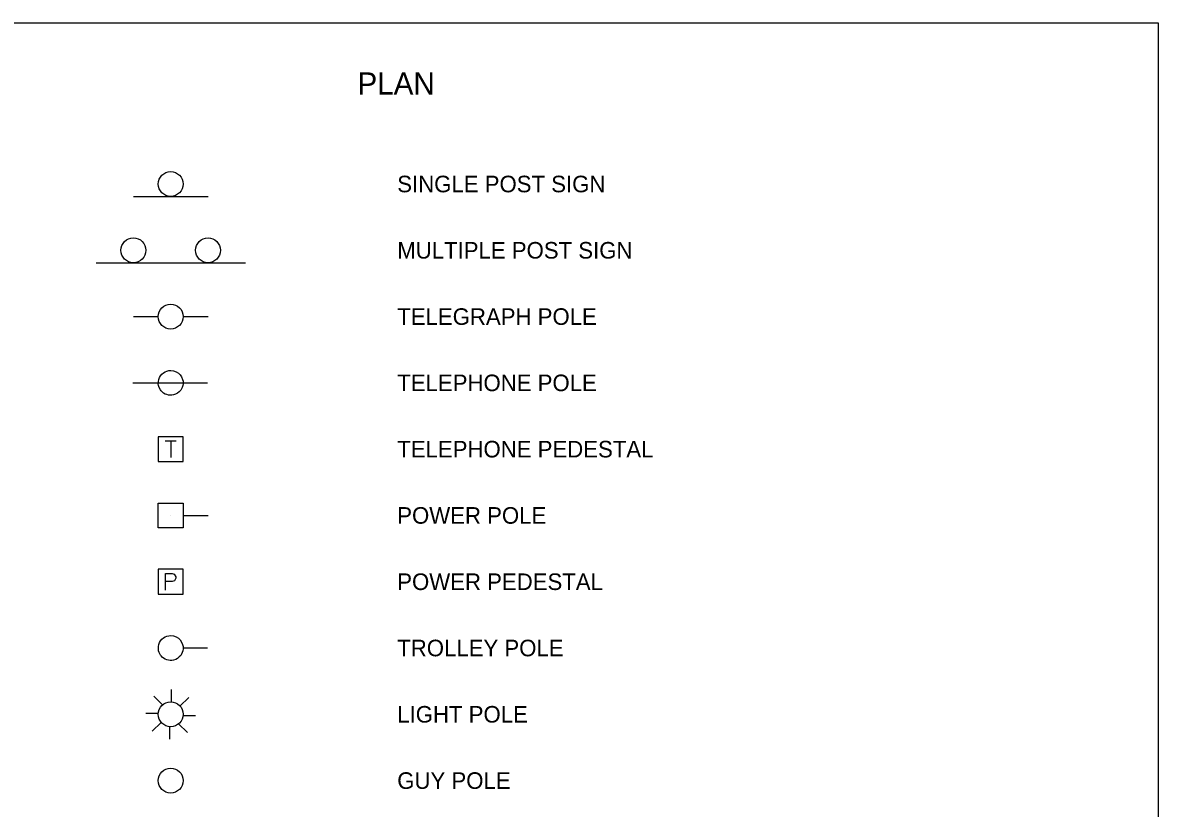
# Model space of a CAD drawing. Extents: x 49991.4 to 50021, y 49987.6 to 50011.4.
# Drawn here: x 50012.64 to 50016.75, y 49996.155 to 49998.999 of the extents above; entities that cross this region are included whole.
import ezdxf

# ---------------------------------------------------------------- set-up
doc = ezdxf.new("R2010")
doc.units = 0
doc.layers.add('Level 1', color=7, linetype='Continuous')
doc.layers.add('Level 2', color=7, linetype='Continuous')

msp = doc.modelspace()

# ---------------------------------------------------------------- linework, layer by layer
at = {"layer": 'Level 1'}
for p, q in [((50013.0405, 49998.3702), (50013.3105, 49998.3702)), ((50012.9055, 49998.1302), (50013.4455, 49998.1302)), ((50013.0403, 49997.9352), (50013.1303, 49997.9352)), ((50013.2203, 49997.9352), (50013.3103, 49997.9352)), ((50013.1306, 49997.7001), (50013.1321, 49997.7079)), ((50013.1321, 49997.7079), (50013.1348, 49997.715)), ((50013.1348, 49997.715), (50013.1381, 49997.7206)), ((50013.1381, 49997.7206), (50013.1431, 49997.7267)), ((50013.1431, 49997.7267), (50013.1488, 49997.7317)), ((50013.1488, 49997.7317), (50013.1551, 49997.7355)), ((50013.1551, 49997.7355), (50013.1612, 49997.7379)), ((50013.1612, 49997.7379), (50013.1684, 49997.7397)), ((50013.1684, 49997.7397), (50013.1758, 49997.7402)), ((50013.1758, 49997.7402), (50013.1854, 49997.7391)), ((50013.1854, 49997.7391), (50013.195, 49997.7357)), ((50013.195, 49997.7357), (50013.2034, 49997.7303)), ((50013.2034, 49997.7303), (50013.2095, 49997.7244)), ((50013.2095, 49997.7244), (50013.2148, 49997.7168)), ((50013.2148, 49997.7168), (50013.2185, 49997.7078)), ((50013.2185, 49997.7078), (50013.2199, 49997.7011)), ((50013.038, 49997.6956), (50013.308, 49997.6956)), ((50013.1304, 49997.6919), (50013.1306, 49997.7001)), ((50013.1314, 49997.6852), (50013.1304, 49997.6919)), ((50013.1335, 49997.6789), (50013.1314, 49997.6852)), ((50013.1381, 49997.6698), (50013.1335, 49997.6789)), ((50013.1407, 49997.6664), (50013.1381, 49997.6698)), ((50013.1446, 49997.6623), (50013.1407, 49997.6664)), ((50013.1495, 49997.6583), (50013.1446, 49997.6623)), ((50013.2064, 49997.6627), (50013.2001, 49997.6577)), ((50013.2114, 49997.6685), (50013.2064, 49997.6627)), ((50013.2146, 49997.6733), (50013.2114, 49997.6685)), ((50013.2171, 49997.6786), (50013.2146, 49997.6733)), ((50013.2192, 49997.6853), (50013.2171, 49997.6786)), ((50013.2202, 49997.6919), (50013.2192, 49997.6853)), ((50013.2199, 49997.7011), (50013.2203, 49997.6955)), ((50013.2203, 49997.6955), (50013.2202, 49997.6919)), ((50013.1554, 49997.6545), (50013.1495, 49997.6583)), ((50013.1612, 49997.6525), (50013.1554, 49997.6545)), ((50013.1671, 49997.651), (50013.1612, 49997.6525)), ((50013.1731, 49997.6503), (50013.1671, 49997.651)), ((50013.1791, 49997.6504), (50013.1731, 49997.6503)), ((50013.1851, 49997.6513), (50013.1791, 49997.6504)), ((50013.1932, 49997.654), (50013.1851, 49997.6513)), ((50013.2001, 49997.6577), (50013.1932, 49997.654)), ((50013.2203, 49997.5002), (50013.1303, 49997.5002)), ((50013.1303, 49997.5002), (50013.1303, 49997.4102)), ((50013.2203, 49997.4102), (50013.2203, 49997.5002)), ((50013.1557, 49997.4852), (50013.1949, 49997.4852)), ((50013.1755, 49997.4852), (50013.1755, 49997.4252)), ((50013.1303, 49997.4102), (50013.2203, 49997.4102)), ((50013.1303, 49997.1702), (50013.1303, 49997.2602)), ((50013.1303, 49997.2602), (50013.2203, 49997.2602)), ((50013.2203, 49997.2602), (50013.2203, 49997.1702)), ((50013.1753, 49997.2152), (50013.1753, 49997.2152)), ((50013.2203, 49997.2152), (50013.3103, 49997.2152)), ((50013.2203, 49997.1702), (50013.1303, 49997.1702)), ((50013.2203, 49997.0202), (50013.1303, 49997.0202)), ((50013.1303, 49997.0202), (50013.1303, 49996.9302)), ((50013.1567, 49996.9452), (50013.1567, 49997.0052)), ((50013.1567, 49997.0052), (50013.1808, 49997.0052)), ((50013.1808, 49997.0052), (50013.1879, 49997.0029)), ((50013.1879, 49997.0029), (50013.194, 49996.9934)), ((50013.2203, 49996.9302), (50013.2203, 49997.0202)), ((50013.1808, 49996.976), (50013.1567, 49996.976)), ((50013.1884, 49996.9783), (50013.1808, 49996.976)), ((50013.194, 49996.9878), (50013.1884, 49996.9783)), ((50013.194, 49996.9934), (50013.194, 49996.9878)), ((50013.1303, 49996.9302), (50013.2203, 49996.9302)), ((50013.1349, 49996.7551), (50013.1382, 49996.7607)), ((50013.1382, 49996.7607), (50013.1431, 49996.7667)), ((50013.1431, 49996.7667), (50013.1489, 49996.7717)), ((50013.1489, 49996.7717), (50013.1552, 49996.7755)), ((50013.1552, 49996.7755), (50013.1612, 49996.778)), ((50013.1612, 49996.778), (50013.1685, 49996.7797)), ((50013.1685, 49996.7797), (50013.1758, 49996.7803)), ((50013.1758, 49996.7803), (50013.1854, 49996.7791)), ((50013.1854, 49996.7791), (50013.195, 49996.7757)), ((50013.195, 49996.7757), (50013.2034, 49996.7704)), ((50013.2034, 49996.7704), (50013.2096, 49996.7644)), ((50013.2096, 49996.7644), (50013.2148, 49996.7568)), ((50013.2148, 49996.7568), (50013.2185, 49996.7478)), ((50013.1305, 49996.732), (50013.1306, 49996.7401)), ((50013.1315, 49996.7252), (50013.1305, 49996.732)), ((50013.1306, 49996.7401), (50013.1321, 49996.7479)), ((50013.1335, 49996.7189), (50013.1315, 49996.7252)), ((50013.1321, 49996.7479), (50013.1349, 49996.7551)), ((50013.1382, 49996.7098), (50013.1335, 49996.7189)), ((50013.2171, 49996.7186), (50013.2146, 49996.7134)), ((50013.2192, 49996.7254), (50013.2171, 49996.7186)), ((50013.2185, 49996.7478), (50013.2199, 49996.7411)), ((50013.2202, 49996.7319), (50013.2192, 49996.7254)), ((50013.2199, 49996.7411), (50013.2203, 49996.7355)), ((50013.2203, 49996.7355), (50013.2202, 49996.7319)), ((50013.2203, 49996.7356), (50013.3081, 49996.7356)), ((50013.1408, 49996.7064), (50013.1382, 49996.7098)), ((50013.1447, 49996.7023), (50013.1408, 49996.7064)), ((50013.1496, 49996.6984), (50013.1447, 49996.7023)), ((50013.1555, 49996.6945), (50013.1496, 49996.6984)), ((50013.1612, 49996.6925), (50013.1555, 49996.6945)), ((50013.1671, 49996.691), (50013.1612, 49996.6925)), ((50013.1732, 49996.6903), (50013.1671, 49996.691)), ((50013.1791, 49996.6904), (50013.1732, 49996.6903)), ((50013.1852, 49996.6914), (50013.1791, 49996.6904)), ((50013.1933, 49996.694), (50013.1852, 49996.6914)), ((50013.2002, 49996.6977), (50013.1933, 49996.694)), ((50013.2064, 49996.7027), (50013.2002, 49996.6977)), ((50013.2115, 49996.7085), (50013.2064, 49996.7027)), ((50013.2146, 49996.7134), (50013.2115, 49996.7085)), ((50013.1453, 49996.5292), (50013.1136, 49996.561)), ((50013.1782, 49996.5398), (50013.1782, 49996.5848)), ((50013.2089, 49996.5241), (50013.2407, 49996.5559)), ((50013.1297, 49996.4985), (50013.0847, 49996.4985)), ((50013.2195, 49996.4913), (50013.2645, 49996.4913)), ((50013.1403, 49996.4656), (50013.1084, 49996.4338)), ((50013.171, 49996.45), (50013.171, 49996.405)), ((50013.2038, 49996.4606), (50013.2356, 49996.4287))]:
    msp.add_line(p, q, dxfattribs=at)
msp.add_lwpolyline([(49999.3835, 49998.9992), (50016.7501, 49998.9992), (50016.7501, 49987.7988), (49999.3835, 49987.7988)], close=True, dxfattribs=at)
for centre in [(50013.1753, 49998.4152), (50013.0403, 49998.1752), (50013.3103, 49998.1752), (50013.1753, 49997.9352), (50013.1753, 49997.9352), (50013.1753, 49996.4953), (50013.1753, 49996.2552)]:
    msp.add_circle(centre, 0.045, dxfattribs=at)

# ---------------------------------------------------------------- texts
at = {"layer": 'Level 2'}
for s, height, p in [('PLAN', 0.08, (50013.8515, 49998.7392)), ('SINGLE POST SIGN                        ', 0.059999, (50013.9953, 49998.3852)), ('MULTIPLE POST SIGN                      ', 0.059999, (50013.9953, 49998.1452)), ('TELEGRAPH POLE                          ', 0.059999, (50013.9953, 49997.9052)), ('TELEPHONE POLE                          ', 0.059999, (50013.9953, 49997.6652)), ('TELEPHONE PEDESTAL                      ', 0.059999, (50013.9953, 49997.4252)), ('POWER POLE                              ', 0.059999, (50013.9953, 49997.1852)), ('POWER PEDESTAL                          ', 0.059999, (50013.9953, 49996.9452)), ('TROLLEY POLE                            ', 0.059999, (50013.9953, 49996.7052)), ('LIGHT POLE                              ', 0.059999, (50013.9953, 49996.4652)), ('GUY POLE                                ', 0.059999, (50013.9953, 49996.2252))]:
    msp.add_text(s, height=height, dxfattribs=at).set_placement(p)

doc.saveas('drawing.dxf')
